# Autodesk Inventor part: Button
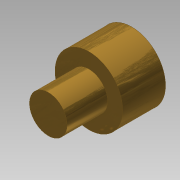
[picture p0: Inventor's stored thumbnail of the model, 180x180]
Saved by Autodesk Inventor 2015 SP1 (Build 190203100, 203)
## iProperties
Created: 2015-05
Part Number: Button
Material: Nylon 6/6
Document SubType Name: Modeling
Designer: kazys
Density: 1.13 g/cm^3
Appearance: Brass - Satin
Author: kazys
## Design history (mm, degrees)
sketch "Sketch1"
  geometry: C1 r 3.81 at (0, 0); 1 further point
  constraints: 1 centre point, 1 coincident
  dimensions: "d13" = 7.62 diameter of C1
extrude "Extrusion1" new body sketch "Sketch1" distance "d0" = 4.826; taper "d1" = 0 deg
sketch "Sketch2"
  geometry: C1 r 2.115 at (0, 0); 1 further point
  constraints: 1 centre point, 1 coincident
  dimensions: "d14" = 4.2291 diameter of C1
extrude "Extrusion2" join sketch "Sketch2" distance "d2" = 4.572; taper "d3" = 0 deg
body "Solid1"
